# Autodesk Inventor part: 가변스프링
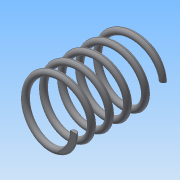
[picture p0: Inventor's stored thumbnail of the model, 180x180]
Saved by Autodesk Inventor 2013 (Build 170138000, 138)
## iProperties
Created: 2017-12
Part Number: 가변스프링
Material: 일반
Document SubType Name: Modeling
Designer: Administrator
Density: 1 g/cm^3
Author: Administrator
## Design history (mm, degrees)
sketch "스케치1"
  geometry: L1 (9, 0)-(0, 0); L2 (0, 0)-(0, 28.5); L3 (0, 28.5)-(9, 28.5); C1 r 1 at (9, 0)
  constraints: 6 end point, 1 centre point, 1 coincident, 1 horizontal, 1 parallel, 1 perpendicular
  dimensions: "d0" = 28.5 distance of L1.end L2.end (derived); "d1" = 9 distance of L2.end L3.end; "d2" = 9 distance of L1.start L1.end; "d3" = 2 diameter of C1
feature "코일1" sketch "스케치1" pitch "d4" = 10; turns "d6" = 5; dims "d5" = 28.5 (= d0), "d7" = 0, angle "d8" = 90 deg, angle "d9" = 90 deg, "d10" = 0, "d11" = 0
sketch "스케치2"
  geometry: L1 (28.5, 15)-(0, 15); L2 (0, 15)-(0, -15); L3 (0, -15)-(28.5, -15); L4 (28.5, -15)-(28.5, 15); 2 further points
  constraints: 8 end point, 2 parallel, 1 coincident, 1 horizontal, 1 midpoint, 1 perpendicular
  dimensions: "d12" = 28.5 distance of L2.end L3.end (derived); "d14" = 30 distance of L3.end L1.start
extrude "돌출1" sketch "스케치2" stored distance "d15" = 0; taper "d16" = 0 deg
node "솔리드1"
